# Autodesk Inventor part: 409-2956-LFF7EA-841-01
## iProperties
Created: 2010-09
Part Number: 409-2956-LFF7EA-841-01
Material: 1/2"OD TUBE - SS
Document SubType Name: Modeling
Designer: S. Boerckel
Engineer: Steve Boerckel
Mass: 246.219 g
Surface Area: 534.036 cm^2
Volume: 30.4727 cm^3
Density: 8.08 g/cm^3
Description: BACK PRESSURE TUBE
Length: 28.909 in
Author: S. Boerckel
Revision Number: 0
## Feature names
1. Sweep2
